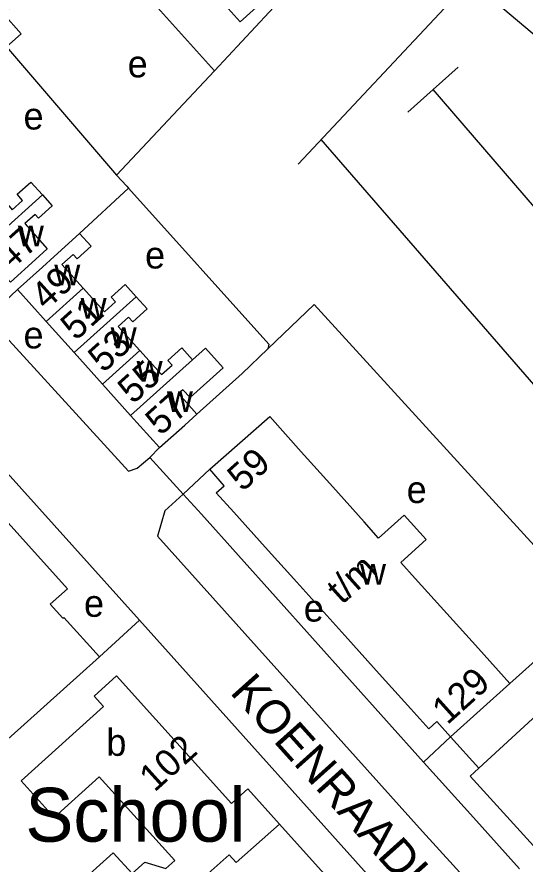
# Model space of a CAD drawing. Extents: x 158356 to 159894, y 383831 to 385260.
# Drawn here: x 159131.9 to 159207.3, y 384085.1 to 384210.9 of the extents above; entities that cross this region are included whole.
import ezdxf

# ---------------------------------------------------------------- set-up
doc = ezdxf.new("R2010")
doc.units = 0
for name, color, linetype in [('BLT_Basislijn', 7, 'Continuous'), ('BLT_Bebouwing', 7, 'Continuous'), ('BLT_Bebouwing_beschrifting', 7, 'Continuous'), ('BLT_Centroide', 7, 'Continuous'), ('BLT_Huisnummer', 7, 'Continuous'), ('BLT_Huisnummer_ tussenligend', 7, 'Continuous'), ('BLT_Huisnummer_reeks', 7, 'Continuous'), ('BLT_Onderverdeling_panden', 7, 'Continuous'), ('BLT_Straatnaam', 7, 'Continuous')]:
    doc.layers.add(name, color=color, linetype=linetype)

msp = doc.modelspace()

# ---------------------------------------------------------------- linework, layer by layer
at = {"layer": 'BLT_Basislijn'}
for p, q in [((159186.36, 384229.83), (159161.21, 384202.88)), ((159145.77, 384220.13), (159161.21, 384202.88)), ((159199.22, 384216.28), (159173.63, 384189.04)), ((159199.22, 384216.28), (159231.79, 384188.8)), ((159130.32, 384206.45), (159146.69, 384187.41)), ((159197.41, 384203.43), (159193.68, 384200.1)), ((159161.21, 384202.88), (159146.69, 384187.41)), ((159193.68, 384200.1), (159189.95, 384196.76)), ((159217.11, 384172.93), (159193.68, 384200.1)), ((159217.23, 384146.36), (159177.07, 384192.7)), ((159141.2, 384178.73), (159148.48, 384185.47)), ((159127.56, 384166.25), (159131.96, 384170.41)), ((159169.16, 384161.61), (159176.04, 384168.18)), ((159176.04, 384168.18), (159217.33, 384122.92)), ((159153.08, 384146.94), (159151.61, 384145.46)), ((159151.61, 384145.46), (159156.58, 384140.01)), ((159160.54, 384143.71), (159156.58, 384140.01)), ((159156.58, 384140.01), (159153.87, 384137.53)), ((159153.87, 384137.53), (159152.77, 384133.76)), ((159152.77, 384133.76), (159192.14, 384089.95)), ((159205.1, 384111.92), (159217.33, 384122.92)), ((159144.13, 384115.88), (159150.1, 384121.32)), ((159196.3, 384104), (159192.28, 384100.24)), ((159196.3, 384104), (159200.49, 384099.35)), ((159192.28, 384100.24), (159199.69, 384091.99)), ((159199.69, 384091.99), (159206.51, 384084.38)), ((159192.14, 384089.95), (159204.25, 384076.61))]:
    msp.add_line(p, q, dxfattribs=at)
for points in [[(159146.69, 384187.41), (159148.21, 384185.77), (159148.48, 384185.47)], [(159148.48, 384185.47), (159169.32, 384162.31), (159169.16, 384161.61)], [(159127.56, 384166.25), (159148.47, 384143.45), (159149.77, 384143.87), (159151.61, 384145.46)], [(159169.16, 384161.61), (159165.34, 384157.96), (159158.61, 384151.91)], [(159150.1, 384121.32), (159130.02, 384143.68), (159120.6, 384153.86), (159119.28, 384154.91), (159118.85, 384154.94), (159100, 384137.59), (159095.43, 384132.92)], [(159156.58, 384140.01), (159159.29, 384137.04), (159192.28, 384100.24)], [(159150.1, 384121.32), (159190.71, 384075.98), (159191.11, 384075.54)]]:
    msp.add_lwpolyline(points, dxfattribs=at)
at = {"layer": 'BLT_Bebouwing'}
for p, q in [((159131.96, 384170.41), (159136.23, 384165.66)), ((159136.23, 384165.66), (159140.39, 384161.04)), ((159140.39, 384161.04), (159144.6, 384156.37)), ((159144.6, 384156.37), (159148.78, 384151.72)), ((159148.78, 384151.72), (159153.08, 384146.94)), ((159178.79, 384141.12), (159174.12, 384146.33)), ((159183.46, 384135.91), (159178.79, 384141.12)), ((159164.08, 384137.35), (159168.77, 384132.15)), ((159168.77, 384132.15), (159173.45, 384126.94)), ((159173.45, 384126.94), (159181.02, 384118.54)), ((159195.72, 384122.31), (159191.03, 384127.51)), ((159200.41, 384117.12), (159195.72, 384122.31)), ((159181.02, 384118.54), (159185.7, 384113.34)), ((159205.1, 384111.92), (159200.41, 384117.12)), ((159144.13, 384115.88), (159130.56, 384103.62)), ((159185.7, 384113.34), (159190.39, 384108.14)), ((159196.3, 384104), (159205.1, 384111.92)), ((159200.49, 384099.35), (159210.53, 384108.6)), ((159200.49, 384099.35), (159199.19, 384098.16)), ((159170.89, 384091.03), (159187.7, 384072.36))]:
    msp.add_line(p, q, dxfattribs=at)
for points in [[(159155.23, 384221.12), (159165.02, 384210.17), (159169.8, 384214.45), (159158.78, 384226.78)], [(159131.65, 384212.92), (159129.88, 384211.33), (159132.51, 384208.4), (159130.32, 384206.45)], [(159128.09, 384185.96), (159131.2, 384182.26), (159132.74, 384183.65), (159131.93, 384184.55), (159133.95, 384186.37), (159135.69, 384184.45)], [(159135.69, 384184.45), (159137.14, 384182.83), (159135.1, 384180.99), (159134.58, 384181.56), (159133.06, 384180.2), (159136.39, 384176.43), (159134.65, 384174.85), (159130.93, 384171.5), (159126.62, 384176.29)], [(159141.2, 384178.73), (159137.43, 384175.33), (159135.68, 384173.75), (159131.96, 384170.41)], [(159141.2, 384178.73), (159142.91, 384176.83), (159140.84, 384174.96), (159140.24, 384175.62), (159138.57, 384174.12), (159141.73, 384170.61)], [(159141.73, 384170.61), (159144.89, 384167.11), (159146.51, 384168.57), (159145.88, 384169.26), (159147.98, 384171.15), (159149.61, 384169.34)], [(159149.61, 384169.34), (159151.24, 384167.53), (159149.12, 384165.62), (159148.48, 384166.32), (159146.92, 384164.91), (159150.13, 384161.34)], [(159150.13, 384161.34), (159153.34, 384157.78), (159154.92, 384159.19), (159154.31, 384159.87), (159156.37, 384161.73), (159157.95, 384159.97)], [(159157.95, 384159.97), (159159.91, 384161.68), (159162.52, 384158.79), (159157.6, 384154.36), (159156.54, 384155.52), (159155.89, 384154.95), (159158.61, 384151.91)], [(159153.08, 384146.94), (159156.8, 384150.29), (159158.61, 384151.91)], [(159160.54, 384143.71), (159169.45, 384151.55), (159174.12, 384146.33)], [(159097.39, 384130.84), (159118.12, 384149.56), (159139.41, 384125.98), (159136.84, 384123.68), (159138.72, 384121.6), (159138.86, 384121.72), (159144.13, 384115.88)], [(159164.08, 384137.35), (159161.49, 384140.23), (159162.69, 384141.28), (159160.54, 384143.71)], [(159191.03, 384127.51), (159188.88, 384129.89), (159192.68, 384133.27), (159189.4, 384136.91), (159185.6, 384133.51), (159183.46, 384135.91)], [(159155.32, 384085.64), (159144.11, 384098.03), (159137.42, 384092), (159132.5, 384097.47), (159144.75, 384108.5), (159143.36, 384110.04), (159146.69, 384113.04), (159163.75, 384094.1), (159166.17, 384096.27), (159170.89, 384091.03)], [(159190.39, 384108.14), (159193.06, 384105.17), (159194.25, 384106.26), (159196.3, 384104)], [(159227.86, 384073.32), (159223.22, 384073.57), (159223.51, 384082.82), (159219.74, 384082.98), (159219.55, 384075.78), (159199.19, 384098.16)], [(159135.19, 384076.87), (159146.19, 384086.78), (159149, 384083.71), (159150.86, 384085.39), (159154.01, 384084.46), (159155.32, 384085.64)]]:
    msp.add_lwpolyline(points, dxfattribs=at)
at = {"layer": 'BLT_Onderverdeling_panden'}
for p, q in [((159135.69, 384184.45), (159126.62, 384176.29)), ((159141.73, 384170.61), (159136.23, 384165.66)), ((159149.61, 384169.34), (159140.39, 384161.04)), ((159150.13, 384161.34), (159144.6, 384156.37)), ((159157.95, 384159.97), (159148.78, 384151.72))]:
    msp.add_line(p, q, dxfattribs=at)
msp.add_lwpolyline([(159158.52, 384082.1), (159163.43, 384086.47), (159164.43, 384085.34), (159170.89, 384091.03)], dxfattribs=at)

# ---------------------------------------------------------------- texts
at = {"layer": 'BLT_Bebouwing_beschrifting'}
msp.add_text('School', height=8, rotation=359.9995, dxfattribs=at).set_placement((159133.14, 384088.42))
at = {"layer": 'BLT_Centroide'}
for s, p in [('e', (159148.34, 384201.91)), ('e', (159132.87, 384194.17)), ('w', (159132.02, 384176.8)), ('e', (159150.92, 384173.53)), ('w', (159137.44, 384171.05)), ('w', (159141.35, 384166.09)), ('e', (159132.87, 384161.66)), ('w', (159145.81, 384161.7)), ('w', (159149.66, 384156.72)), ('w', (159154.16, 384152.23)), ('e', (159189.77, 384138.7)), ('w', (159182.83, 384126.58)), ('e', (159141.85, 384121.81)), ('e', (159174.49, 384121.1)), ('b', (159145.17, 384101.17))]:
    msp.add_text(s, height=4, dxfattribs=at).set_placement(p)
at = {"layer": 'BLT_Huisnummer'}
for s, rotation, p in [('47', 41.9821, (159130.93, 384173.13)), ('49', 41.9821, (159136.23, 384167.22)), ('53', 41.9821, (159144.71, 384157.92)), ('57', 41.9821, (159153.22, 384148.58)), ('102', 42.0279, (159152.32, 384095.67))]:
    msp.add_text(s, height=4, rotation=rotation, dxfattribs=at).set_placement(p)
at = {"layer": 'BLT_Huisnummer_ tussenligend'}
for s, p in [('51', (159140.63, 384162.69)), ('55', (159149.12, 384153.27))]:
    msp.add_text(s, height=4, rotation=41.9821, dxfattribs=at).set_placement(p)
at = {"layer": 'BLT_Huisnummer_reeks'}
for s, p in [('59', (159165.39, 384140.27)), ('t/m', (159180.15, 384123.52)), ('129', (159195.8, 384105.67))]:
    msp.add_text(s, height=4, rotation=41.9807, dxfattribs=at).set_placement(p)
at = {"layer": 'BLT_Straatnaam'}
msp.add_text('KOENRAADLAAN', height=5, rotation=311.8995, dxfattribs=at).set_placement((159163.4, 384110.53))

doc.saveas('drawing.dxf')
